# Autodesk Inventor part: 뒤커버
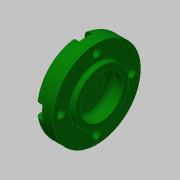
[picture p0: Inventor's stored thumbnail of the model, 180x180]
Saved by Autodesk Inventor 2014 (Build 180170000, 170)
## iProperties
Created: 2015-11
Part Number: 뒤커버
Material: 알루미늄 6061
Document SubType Name: Modeling
Designer: mduedu
Density: 1 g/cm^3
Appearance: Dark Green
Author: mduedu
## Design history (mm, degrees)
sketch "스케치1"
  geometry: L1 (-7, 0)-(7, 0); L2 (-7, 0)-(-7, 26); L3 (-7, 26)-(4, 26); L4 (4, 26)-(4, 16); L5 (4, 16)-(7, 16); L6 (7, 16)-(7, 0); 2 further points
  constraints: 12 end point, 3 perpendicular, 2 parallel, 1 coincident, 1 horizontal, 1 midpoint
  dimensions: "d0" = 14 distance of L1.start L1.end; "d1" = 52 diameter of L3 L1; "d2" = 3 distance of L4.end L5.end; "d3" = 32 diameter of L5 L1
revolve "회전1" sketch "스케치1" stored, may be unused: angle "d4" = 90 deg
hole "구멍1" diameter "d7" = 25; stored, may be unused: countersink angle "d11" = 90 deg, drill point angle "d13" = 0 deg; dims "d8" = 6, "d9" = 4, "d10" = 2, "d12" = 8, "d62" = 10, "d63" = 10
fillet "모깎기2" dims "d36" = 3
fillet "모깎기3" dims "d37" = 3
fillet "모깎기4" dims "d38" = 0.3
sketch "스케치3" dims "d61" = 42
  geometry: C1 r 26 at (0, 0) reference; 2 further points
  constraints: 2 vertical alignment, 1 coincident, 2 other
hole "구멍4" sketch "스케치3" at (0, -21) diameter "d44" = 4.5; stored, may be unused: countersink angle "d48" = 90 deg, drill point angle "d50" = 0 deg; dims "d45" = 6, "d46" = 8, "d47" = 4.6, "d49" = 8
sketch "스케치4"
  geometry: L1 (-4, 0)-(-4, -4.69); L2 (4, 0)-(4, -4.69); A1 r 4 centre (0, 0) between (3.614, -1.714) and (-3.614, -1.714) reference; A2 r 26 centre (0, 21) between (-4, -4.69) and (4, -4.69) reference; 1 further point
  constraints: 4 end point, 4 point on circle, 2 tangent, 1 parallel, 1 vertical
extrude "돌출1" cut sketch "스케치4" stored distance "d51" = 0; taper "d52" = 0 deg
node "솔리드1"
pattern_circular "원형 패턴1" dims angle "d54" = 360 deg
